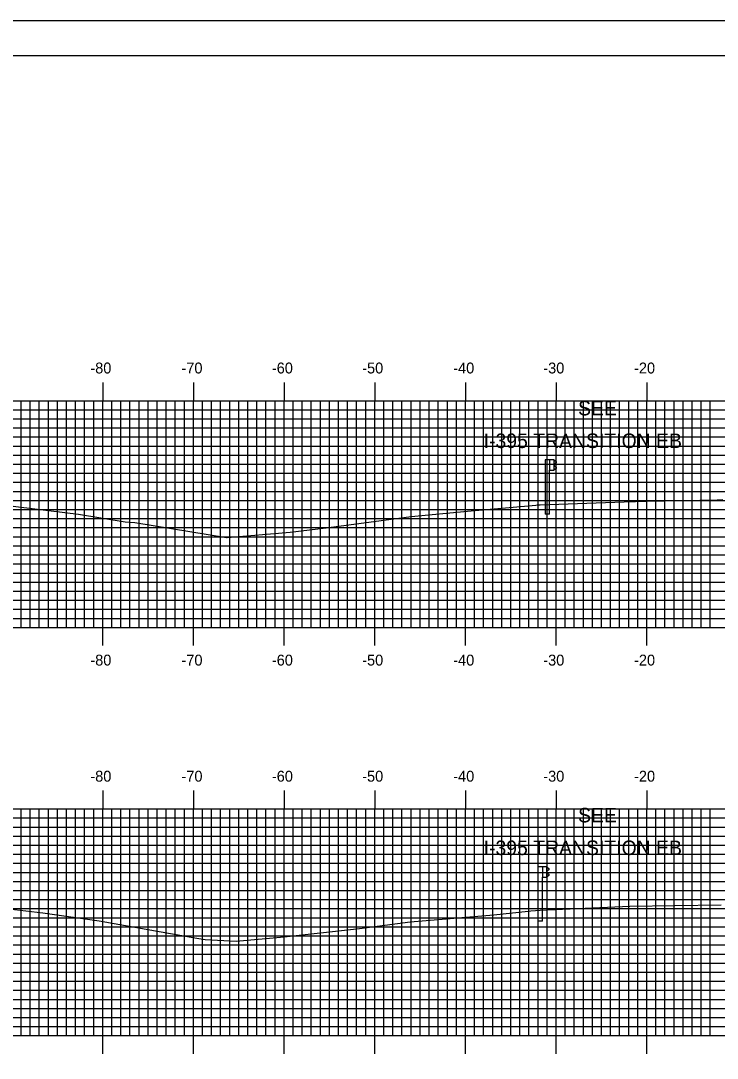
# Model space of a CAD drawing. Extents: x 842962 to 843305, y 363538 to 363758.
# Drawn here: x 843038.9 to 843115.7, y 363643.2 to 363757.6 of the extents above; entities that cross this region are included whole.
import ezdxf

# ---------------------------------------------------------------- set-up
doc = ezdxf.new("R2010")
doc.units = 0
for name, color, linetype in [('ANNOTATION', 7, 'Continuous'), ('BORDER', 7, 'Continuous'), ('H_V ANNOTATION', 7, 'Continuous'), ('M_Guardrail', 7, 'Continuous'), ('MAJOR', 7, 'Continuous'), ('MINOR', 7, 'Continuous'), ('PLOT BOUNDARY', 7, 'Continuous'), ('S_Roadway_Centerline', 7, 'Continuous')]:
    doc.layers.add(name, color=color, linetype=linetype)

msp = doc.modelspace()

# ---------------------------------------------------------------- linework, layer by layer
at = {"layer": 'BORDER'}
msp.add_lwpolyline([(842978.31, 363543.72), (843298.31, 363543.72), (843298.31, 363753.72), (842978.31, 363753.72)], close=True, dxfattribs=at)
at = {"layer": 'M_Guardrail'}
for p, q in [((843096.7, 363709.21), (843096.7, 363703.21)), ((843097.19, 363709.21), (843096.7, 363709.21)), ((843097.68, 363709.21), (843097.19, 363709.21)), ((843097.19, 363709.21), (843097.19, 363708.05)), ((843097.68, 363708.05), (843097.68, 363709.21)), ((843097.68, 363709.14), (843097.76, 363709.13)), ((843097.69, 363708.68), (843097.69, 363708.58)), ((843097.92, 363708.88), (843097.73, 363708.74)), ((843097.73, 363708.52), (843097.92, 363708.38)), ((843097.78, 363709.12), (843097.92, 363709.02)), ((843097.19, 363703.21), (843097.19, 363708.05)), ((843097.19, 363708.05), (843097.68, 363708.05)), ((843097.76, 363708.13), (843097.68, 363708.12)), ((843097.92, 363708.24), (843097.78, 363708.14)), ((843097.19, 363703.21), (843096.7, 363703.21)), ((843095.89, 363664.34), (843095.89, 363658.34)), ((843096.39, 363664.34), (843095.89, 363664.34)), ((843096.88, 363664.34), (843096.39, 363664.34)), ((843096.39, 363664.34), (843096.39, 363663.18)), ((843096.88, 363663.18), (843096.88, 363664.34)), ((843096.88, 363664.27), (843096.96, 363664.25)), ((843096.89, 363663.8), (843096.89, 363663.71)), ((843097.12, 363664), (843096.92, 363663.87)), ((843096.97, 363664.25), (843097.12, 363664.15)), ((843096.39, 363658.34), (843096.39, 363663.18)), ((843096.39, 363663.18), (843096.88, 363663.18)), ((843096.96, 363663.26), (843096.88, 363663.25)), ((843096.92, 363663.65), (843097.12, 363663.51)), ((843097.12, 363663.37), (843096.97, 363663.27)), ((843096.39, 363658.34), (843095.89, 363658.34))]:
    msp.add_line(p, q, dxfattribs=at)
for centre, major_axis, start_param, end_param in [((843097.77, 363708.68), (-0.0789, 0), 5.323254, 6.283185), ((843097.77, 363708.58), (-0.0789, 0), 6.283185, 7.243116), ((843097.75, 363709.09), (0.0417, 0), 0.959931, 1.396263), ((843097.87, 363708.95), (0.0877, 0), 5.323254, 7.243116), ((843097.87, 363708.31), (0.0877, 0), 5.323254, 7.243116), ((843097.75, 363708.17), (0.0417, 0), 4.886922, 5.323254), ((843096.97, 363663.8), (-0.0789, 0), 5.323254, 6.283185), ((843096.95, 363664.21), (0.0417, 0), 0.959931, 1.396263), ((843097.07, 363664.08), (0.0877, 0), 5.323254, 7.243116), ((843096.97, 363663.71), (-0.0789, 0), 6.283185, 7.243116), ((843096.95, 363663.3), (0.0417, 0), 4.886922, 5.323254), ((843097.07, 363663.44), (0.0877, 0), 5.323254, 7.243116)]:
    msp.add_ellipse(centre, major_axis=major_axis, ratio=0.995501, start_param=start_param, end_param=end_param, dxfattribs=at)
at = {"layer": 'MAJOR'}
for p, q in [((843047.91, 363717.73), (843047.91, 363715.72)), ((843057.91, 363717.73), (843057.91, 363715.72)), ((843067.91, 363717.73), (843067.91, 363715.72)), ((843077.91, 363717.73), (843077.91, 363715.72)), ((843087.91, 363717.73), (843087.91, 363715.72)), ((843097.91, 363717.73), (843097.91, 363715.72)), ((843107.91, 363717.73), (843107.91, 363715.72)), ((842987.91, 363715.72), (843267.91, 363715.72)), ((842987.91, 363715.72), (843267.91, 363715.72)), ((843047.91, 363690.72), (843047.91, 363715.72)), ((843057.91, 363690.72), (843057.91, 363715.72)), ((843067.91, 363690.72), (843067.91, 363715.72)), ((843077.91, 363690.72), (843077.91, 363715.72)), ((843087.91, 363690.72), (843087.91, 363715.72)), ((843097.91, 363690.72), (843097.91, 363715.72)), ((843107.91, 363690.72), (843107.91, 363715.72)), ((842987.91, 363710.72), (843267.91, 363710.72)), ((842987.91, 363705.72), (843267.91, 363705.72)), ((842987.91, 363700.72), (843267.91, 363700.72)), ((842987.91, 363695.72), (843267.91, 363695.72)), ((842987.91, 363690.72), (843267.91, 363690.72)), ((842987.91, 363690.72), (843267.91, 363690.72)), ((843047.91, 363688.72), (843047.91, 363690.72)), ((843057.91, 363688.72), (843057.91, 363690.72)), ((843067.91, 363688.72), (843067.91, 363690.72)), ((843077.91, 363688.72), (843077.91, 363690.72)), ((843087.91, 363688.72), (843087.91, 363690.72)), ((843097.91, 363688.72), (843097.91, 363690.72)), ((843107.91, 363688.72), (843107.91, 363690.72)), ((843047.91, 363672.73), (843047.91, 363670.72)), ((843057.91, 363672.73), (843057.91, 363670.72)), ((843067.91, 363672.73), (843067.91, 363670.72)), ((843077.91, 363672.73), (843077.91, 363670.72)), ((843087.91, 363672.73), (843087.91, 363670.72)), ((843097.91, 363672.73), (843097.91, 363670.72)), ((843107.91, 363672.73), (843107.91, 363670.72)), ((842987.91, 363670.72), (843267.91, 363670.72)), ((842987.91, 363670.72), (843267.91, 363670.72)), ((843047.91, 363645.72), (843047.91, 363670.72)), ((843057.91, 363645.72), (843057.91, 363670.72)), ((843067.91, 363645.72), (843067.91, 363670.72)), ((843077.91, 363645.72), (843077.91, 363670.72)), ((843087.91, 363645.72), (843087.91, 363670.72)), ((843097.91, 363645.72), (843097.91, 363670.72)), ((843107.91, 363645.72), (843107.91, 363670.72)), ((842987.91, 363665.72), (843267.91, 363665.72)), ((842987.91, 363660.72), (843267.91, 363660.72)), ((842987.91, 363655.72), (843267.91, 363655.72)), ((842987.91, 363650.72), (843267.91, 363650.72)), ((842987.91, 363645.72), (843267.91, 363645.72)), ((842987.91, 363645.72), (843267.91, 363645.72)), ((843047.91, 363643.72), (843047.91, 363645.72)), ((843057.91, 363643.72), (843057.91, 363645.72)), ((843067.91, 363643.72), (843067.91, 363645.72)), ((843077.91, 363643.72), (843077.91, 363645.72)), ((843087.91, 363643.72), (843087.91, 363645.72)), ((843097.91, 363643.72), (843097.91, 363645.72)), ((843107.91, 363643.72), (843107.91, 363645.72))]:
    msp.add_line(p, q, dxfattribs=at)
at = {"layer": 'MINOR'}
for p, q in [((843038.91, 363690.72), (843038.91, 363715.72)), ((843039.91, 363690.72), (843039.91, 363715.72)), ((843040.91, 363690.72), (843040.91, 363715.72)), ((843041.91, 363690.72), (843041.91, 363715.72)), ((843042.91, 363690.72), (843042.91, 363715.72)), ((843043.91, 363690.72), (843043.91, 363715.72)), ((843044.91, 363690.72), (843044.91, 363715.72)), ((843045.91, 363690.72), (843045.91, 363715.72)), ((843046.91, 363690.72), (843046.91, 363715.72)), ((843048.91, 363690.72), (843048.91, 363715.72)), ((843049.91, 363690.72), (843049.91, 363715.72)), ((843050.91, 363690.72), (843050.91, 363715.72)), ((843051.91, 363690.72), (843051.91, 363715.72)), ((843052.91, 363690.72), (843052.91, 363715.72)), ((843053.91, 363690.72), (843053.91, 363715.72)), ((843054.91, 363690.72), (843054.91, 363715.72)), ((843055.91, 363690.72), (843055.91, 363715.72)), ((843056.91, 363690.72), (843056.91, 363715.72)), ((843058.91, 363690.72), (843058.91, 363715.72)), ((843059.91, 363690.72), (843059.91, 363715.72)), ((843060.91, 363690.72), (843060.91, 363715.72)), ((843061.91, 363690.72), (843061.91, 363715.72)), ((843062.91, 363690.72), (843062.91, 363715.72)), ((843063.91, 363690.72), (843063.91, 363715.72)), ((843064.91, 363690.72), (843064.91, 363715.72)), ((843065.91, 363690.72), (843065.91, 363715.72)), ((843066.91, 363690.72), (843066.91, 363715.72)), ((843068.91, 363690.72), (843068.91, 363715.72)), ((843069.91, 363690.72), (843069.91, 363715.72)), ((843070.91, 363690.72), (843070.91, 363715.72)), ((843071.91, 363690.72), (843071.91, 363715.72)), ((843072.91, 363690.72), (843072.91, 363715.72)), ((843073.91, 363690.72), (843073.91, 363715.72)), ((843074.91, 363690.72), (843074.91, 363715.72)), ((843075.91, 363690.72), (843075.91, 363715.72)), ((843076.91, 363690.72), (843076.91, 363715.72)), ((843078.91, 363690.72), (843078.91, 363715.72)), ((843079.91, 363690.72), (843079.91, 363715.72)), ((843080.91, 363690.72), (843080.91, 363715.72)), ((843081.91, 363690.72), (843081.91, 363715.72)), ((843082.91, 363690.72), (843082.91, 363715.72)), ((843083.91, 363690.72), (843083.91, 363715.72)), ((843084.91, 363690.72), (843084.91, 363715.72)), ((843085.91, 363690.72), (843085.91, 363715.72)), ((843086.91, 363690.72), (843086.91, 363715.72)), ((843088.91, 363690.72), (843088.91, 363715.72)), ((843089.91, 363690.72), (843089.91, 363715.72)), ((843090.91, 363690.72), (843090.91, 363715.72)), ((843091.91, 363690.72), (843091.91, 363715.72)), ((843092.91, 363690.72), (843092.91, 363715.72)), ((843093.91, 363690.72), (843093.91, 363715.72)), ((843094.91, 363690.72), (843094.91, 363715.72)), ((843095.91, 363690.72), (843095.91, 363715.72)), ((843096.91, 363690.72), (843096.91, 363715.72)), ((843098.91, 363690.72), (843098.91, 363715.72)), ((843099.91, 363690.72), (843099.91, 363715.72)), ((843100.91, 363690.72), (843100.91, 363715.72)), ((843101.91, 363690.72), (843101.91, 363715.72)), ((843102.91, 363690.72), (843102.91, 363715.72)), ((843103.91, 363690.72), (843103.91, 363715.72)), ((843104.91, 363690.72), (843104.91, 363715.72)), ((843105.91, 363690.72), (843105.91, 363715.72)), ((843106.91, 363690.72), (843106.91, 363715.72)), ((843108.91, 363690.72), (843108.91, 363715.72)), ((843109.91, 363690.72), (843109.91, 363715.72)), ((843110.91, 363690.72), (843110.91, 363715.72)), ((843111.91, 363690.72), (843111.91, 363715.72)), ((843112.91, 363690.72), (843112.91, 363715.72)), ((843113.91, 363690.72), (843113.91, 363715.72)), ((843114.91, 363690.72), (843114.91, 363715.72)), ((842987.91, 363714.72), (843267.91, 363714.72)), ((842987.91, 363713.72), (843267.91, 363713.72)), ((842987.91, 363712.72), (843267.91, 363712.72)), ((842987.91, 363711.72), (843267.91, 363711.72)), ((842987.91, 363709.72), (843267.91, 363709.72)), ((842987.91, 363708.72), (843267.91, 363708.72)), ((842987.91, 363707.72), (843267.91, 363707.72)), ((842987.91, 363706.72), (843267.91, 363706.72)), ((842987.91, 363704.72), (843267.91, 363704.72)), ((842987.91, 363703.72), (843267.91, 363703.72)), ((842987.91, 363702.72), (843267.91, 363702.72)), ((842987.91, 363701.72), (843267.91, 363701.72)), ((842987.91, 363699.72), (843267.91, 363699.72)), ((842987.91, 363698.72), (843267.91, 363698.72)), ((842987.91, 363697.72), (843267.91, 363697.72)), ((842987.91, 363696.72), (843267.91, 363696.72)), ((842987.91, 363694.72), (843267.91, 363694.72)), ((842987.91, 363693.72), (843267.91, 363693.72)), ((842987.91, 363692.72), (843267.91, 363692.72)), ((842987.91, 363691.72), (843267.91, 363691.72)), ((843038.91, 363645.72), (843038.91, 363670.72)), ((843039.91, 363645.72), (843039.91, 363670.72)), ((843040.91, 363645.72), (843040.91, 363670.72)), ((843041.91, 363645.72), (843041.91, 363670.72)), ((843042.91, 363645.72), (843042.91, 363670.72)), ((843043.91, 363645.72), (843043.91, 363670.72)), ((843044.91, 363645.72), (843044.91, 363670.72)), ((843045.91, 363645.72), (843045.91, 363670.72)), ((843046.91, 363645.72), (843046.91, 363670.72)), ((843048.91, 363645.72), (843048.91, 363670.72)), ((843049.91, 363645.72), (843049.91, 363670.72)), ((843050.91, 363645.72), (843050.91, 363670.72)), ((843051.91, 363645.72), (843051.91, 363670.72)), ((843052.91, 363645.72), (843052.91, 363670.72)), ((843053.91, 363645.72), (843053.91, 363670.72)), ((843054.91, 363645.72), (843054.91, 363670.72)), ((843055.91, 363645.72), (843055.91, 363670.72)), ((843056.91, 363645.72), (843056.91, 363670.72)), ((843058.91, 363645.72), (843058.91, 363670.72)), ((843059.91, 363645.72), (843059.91, 363670.72)), ((843060.91, 363645.72), (843060.91, 363670.72)), ((843061.91, 363645.72), (843061.91, 363670.72)), ((843062.91, 363645.72), (843062.91, 363670.72)), ((843063.91, 363645.72), (843063.91, 363670.72)), ((843064.91, 363645.72), (843064.91, 363670.72)), ((843065.91, 363645.72), (843065.91, 363670.72)), ((843066.91, 363645.72), (843066.91, 363670.72)), ((843068.91, 363645.72), (843068.91, 363670.72)), ((843069.91, 363645.72), (843069.91, 363670.72)), ((843070.91, 363645.72), (843070.91, 363670.72)), ((843071.91, 363645.72), (843071.91, 363670.72)), ((843072.91, 363645.72), (843072.91, 363670.72)), ((843073.91, 363645.72), (843073.91, 363670.72)), ((843074.91, 363645.72), (843074.91, 363670.72)), ((843075.91, 363645.72), (843075.91, 363670.72)), ((843076.91, 363645.72), (843076.91, 363670.72)), ((843078.91, 363645.72), (843078.91, 363670.72)), ((843079.91, 363645.72), (843079.91, 363670.72)), ((843080.91, 363645.72), (843080.91, 363670.72)), ((843081.91, 363645.72), (843081.91, 363670.72)), ((843082.91, 363645.72), (843082.91, 363670.72)), ((843083.91, 363645.72), (843083.91, 363670.72)), ((843084.91, 363645.72), (843084.91, 363670.72)), ((843085.91, 363645.72), (843085.91, 363670.72)), ((843086.91, 363645.72), (843086.91, 363670.72)), ((843088.91, 363645.72), (843088.91, 363670.72)), ((843089.91, 363645.72), (843089.91, 363670.72)), ((843090.91, 363645.72), (843090.91, 363670.72)), ((843091.91, 363645.72), (843091.91, 363670.72)), ((843092.91, 363645.72), (843092.91, 363670.72)), ((843093.91, 363645.72), (843093.91, 363670.72)), ((843094.91, 363645.72), (843094.91, 363670.72)), ((843095.91, 363645.72), (843095.91, 363670.72)), ((843096.91, 363645.72), (843096.91, 363670.72)), ((843098.91, 363645.72), (843098.91, 363670.72)), ((843099.91, 363645.72), (843099.91, 363670.72)), ((843100.91, 363645.72), (843100.91, 363670.72)), ((843101.91, 363645.72), (843101.91, 363670.72)), ((843102.91, 363645.72), (843102.91, 363670.72)), ((843103.91, 363645.72), (843103.91, 363670.72)), ((843104.91, 363645.72), (843104.91, 363670.72)), ((843105.91, 363645.72), (843105.91, 363670.72)), ((843106.91, 363645.72), (843106.91, 363670.72)), ((843108.91, 363645.72), (843108.91, 363670.72)), ((843109.91, 363645.72), (843109.91, 363670.72)), ((843110.91, 363645.72), (843110.91, 363670.72)), ((843111.91, 363645.72), (843111.91, 363670.72)), ((843112.91, 363645.72), (843112.91, 363670.72)), ((843113.91, 363645.72), (843113.91, 363670.72)), ((843114.91, 363645.72), (843114.91, 363670.72)), ((842987.91, 363669.72), (843267.91, 363669.72)), ((842987.91, 363668.72), (843267.91, 363668.72)), ((842987.91, 363667.72), (843267.91, 363667.72)), ((842987.91, 363666.72), (843267.91, 363666.72)), ((842987.91, 363664.72), (843267.91, 363664.72)), ((842987.91, 363663.72), (843267.91, 363663.72)), ((842987.91, 363662.72), (843267.91, 363662.72)), ((842987.91, 363661.72), (843267.91, 363661.72)), ((842987.91, 363659.72), (843267.91, 363659.72)), ((842987.91, 363658.72), (843267.91, 363658.72)), ((842987.91, 363657.72), (843267.91, 363657.72)), ((842987.91, 363656.72), (843267.91, 363656.72)), ((842987.91, 363654.72), (843267.91, 363654.72)), ((842987.91, 363653.72), (843267.91, 363653.72)), ((842987.91, 363652.72), (843267.91, 363652.72)), ((842987.91, 363651.72), (843267.91, 363651.72)), ((842987.91, 363649.72), (843267.91, 363649.72)), ((842987.91, 363648.72), (843267.91, 363648.72)), ((842987.91, 363647.72), (843267.91, 363647.72)), ((842987.91, 363646.72), (843267.91, 363646.72))]:
    msp.add_line(p, q, dxfattribs=at)
at = {"layer": 'PLOT BOUNDARY'}
msp.add_lwpolyline([(842962.12, 363537.6), (843302.12, 363537.6), (843302.12, 363757.6), (842962.12, 363757.6)], close=True, dxfattribs=at)
at = {"layer": 'S_Roadway_Centerline'}
for points in [[(843036.8, 363704.25), (843045.25, 363703.21), (843050.38, 363702.38), (843051.44, 363702.3), (843061.54, 363700.62), (843061.64, 363700.63), (843068.59, 363701.21), (843072.83, 363701.73), (843081.93, 363702.96), (843088.15, 363703.55), (843095.68, 363704.21), (843095.8, 363704.22), (843096.16, 363704.24), (843105.41, 363704.58), (843107.93, 363704.64), (843115.65, 363704.79), (843116.3, 363704.83)], [(843036.93, 363659.78), (843041.29, 363659.27), (843047.53, 363658.38), (843058.27, 363656.47), (843059.19, 363656.33), (843062.61, 363656.14), (843067.92, 363656.6), (843076.24, 363657.52), (843081.81, 363658.27), (843091.02, 363659.04), (843094.82, 363659.44), (843095.12, 363659.49), (843096.16, 363659.55), (843106.04, 363659.98), (843110.99, 363660.08), (843116.11, 363660.15)]]:
    msp.add_lwpolyline(points, dxfattribs=at)

# ---------------------------------------------------------------- texts
at = {"layer": 'ANNOTATION'}
for s, p in [('SEE', (843100.33, 363714.1)), ('I-395 TRANSITION EB', (843089.91, 363710.5)), ('SEE', (843100.33, 363669.23)), ('I-395 TRANSITION EB', (843089.91, 363665.63))]:
    msp.add_text(s, height=1.6, dxfattribs=at).set_placement(p)
at = {"layer": 'H_V ANNOTATION'}
for s, p in [('-80', (843046.54, 363718.72)), ('-70', (843056.59, 363718.72)), ('-60', (843066.56, 363718.72)), ('-50', (843076.52, 363718.72)), ('-40', (843086.56, 363718.72)), ('-30', (843096.49, 363718.72)), ('-20', (843106.5, 363718.72)), ('-80', (843046.54, 363686.52)), ('-70', (843056.59, 363686.52)), ('-60', (843066.56, 363686.52)), ('-50', (843076.52, 363686.52)), ('-40', (843086.56, 363686.52)), ('-30', (843096.49, 363686.52)), ('-20', (843106.5, 363686.52)), ('-80', (843046.54, 363673.72)), ('-70', (843056.59, 363673.72)), ('-60', (843066.56, 363673.72)), ('-50', (843076.52, 363673.72)), ('-40', (843086.56, 363673.72)), ('-30', (843096.49, 363673.72)), ('-20', (843106.5, 363673.72))]:
    msp.add_text(s, height=1.2, dxfattribs=at).set_placement(p)

doc.saveas('drawing.dxf')
